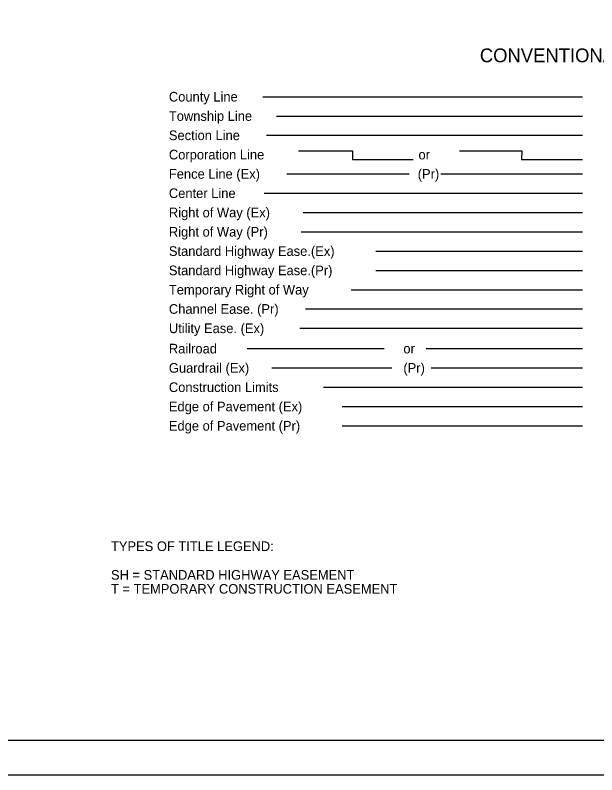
# Model space of a CAD drawing. Extents: x 0 to 59.1, y -2.4 to 22.
# Drawn here: x 8.44 to 16.87, y 0 to 11.02 of the extents above; entities that cross this region are included whole.
import ezdxf

# ---------------------------------------------------------------- set-up
doc = ezdxf.new("R2010")
doc.units = 0
for name, color, linetype in [('SH_Border', 7, 'Continuous'), ('SH_Cut_Line', 7, 'Continuous'), ('SH_Text', 7, 'Continuous')]:
    doc.layers.add(name, color=color, linetype=linetype)

msp = doc.modelspace()

# ---------------------------------------------------------------- linework, layer by layer
at = {"layer": 'SH_Border'}
msp.add_lwpolyline([(1.5, 21.5), (33.5, 21.5), (33.5, 0.5), (1.5, 0.5)], close=True, dxfattribs=at)
at = {"layer": 'SH_Cut_Line'}
msp.add_lwpolyline([(0, 0), (34, 0), (34, 22), (0, 22)], close=True, dxfattribs=at)
at = {"layer": 'SH_Text'}
for p, q in [((12.028, 9.839), (16.667, 9.839)), ((12.226, 9.559), (16.667, 9.559)), ((12.083, 9.279), (16.667, 9.279)), ((12.547, 9.056), (13.33, 9.056)), ((13.33, 9.056), (13.33, 8.929)), ((13.33, 8.929), (14.211, 8.929)), ((12.38, 8.719), (14.153, 8.719)), ((14.61, 8.719), (16.667, 8.719)), ((12.049, 8.439), (16.667, 8.439)), ((12.616, 8.159), (16.667, 8.159)), ((12.588, 7.879), (16.667, 7.879)), ((13.667, 7.599), (16.667, 7.599)), ((13.667, 7.319), (16.667, 7.319)), ((13.312, 7.039), (16.667, 7.039)), ((12.65, 6.759), (16.667, 6.759)), ((12.566, 6.479), (16.667, 6.479)), ((11.805, 6.184), (13.791, 6.184)), ((14.401, 6.184), (16.667, 6.184)), ((12.159, 5.904), (13.902, 5.904)), ((14.472, 5.904), (16.667, 5.904)), ((12.911, 5.624), (16.667, 5.624)), ((13.183, 5.344), (16.667, 5.344)), ((13.183, 5.064), (16.667, 5.064))]:
    msp.add_line(p, q, dxfattribs=at)
msp.add_lwpolyline([(14.884, 9.056), (15.787, 9.056), (15.781, 8.929), (16.667, 8.929)], dxfattribs=at)

# ---------------------------------------------------------------- texts
for s, height, p in [('CONVENTIONAL SYMBOLS', 0.2, (15.178, 10.339)), ('County Line', 0.14, (10.667, 9.769)), ('Township Line', 0.14, (10.667, 9.489)), ('Section Line', 0.14, (10.667, 9.209)), ('Corporation Line                                           or', 0.14, (10.667, 8.929)), ('Fence Line (Ex)                                            (Pr)', 0.14, (10.667, 8.649)), ('Center Line', 0.14, (10.667, 8.369)), ('Right of Way (Ex)', 0.14, (10.667, 8.089)), ('Right of Way (Pr)', 0.14, (10.667, 7.809)), ('Standard Highway Ease.(Ex)', 0.14, (10.667, 7.529)), ('Standard Highway Ease.(Pr)', 0.14, (10.667, 7.249)), ('Temporary Right of Way', 0.14, (10.667, 6.969)), ('Channel Ease. (Pr)', 0.14, (10.667, 6.689)), ('Utility Ease. (Ex)', 0.14, (10.667, 6.409)), ('Railroad                                                    or', 0.14, (10.667, 6.114)), ('Guardrail (Ex)                                           (Pr)', 0.14, (10.667, 5.834)), ('Construction Limits', 0.14, (10.667, 5.554)), ('Edge of Pavement (Ex)', 0.14, (10.667, 5.274)), ('Edge of Pavement (Pr)', 0.14, (10.667, 4.994)), ('TYPES OF TITLE LEGEND:', 0.14, (9.827, 3.247)), ('SH = STANDARD HIGHWAY EASEMENT', 0.14, (9.827, 2.831)), ('T = TEMPORARY CONSTRUCTION EASEMENT', 0.14, (9.827, 2.628))]:
    msp.add_text(s, height=height, dxfattribs=at).set_placement(p)

doc.saveas('drawing.dxf')
